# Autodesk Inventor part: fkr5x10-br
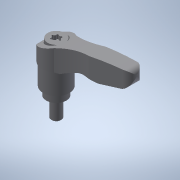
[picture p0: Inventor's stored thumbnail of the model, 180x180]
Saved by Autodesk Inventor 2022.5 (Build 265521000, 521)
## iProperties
Created: 2017-09
Part Number: fkr5x10-br
Material: 一般
Document SubType Name: Modeling
Designer: imaocorp
Density: 1 g/cm^3
Appearance: 既定
Author: imaocorp
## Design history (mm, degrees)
node "fkr5x10-br.x_t1"
node "fkr5x10-br"
node "Base1"
